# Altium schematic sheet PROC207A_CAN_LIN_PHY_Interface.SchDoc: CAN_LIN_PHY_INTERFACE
size 431 x 279 mm; Date: Not shown in title block; ApprovedBy: Not shown in title block; CheckedBy: Not shown in title block; Author: Not shown in title block; CompanyName: Not shown in title block; DrawnBy: Mistral; Engineer: Not shown in title block; Organization: Not shown in title block; Address1: Not shown in title block; Address2: Not shown in title block; Address3: Not shown in title block; Address4: Not shown in title block; DocumentNumber: 13; Revision: Use project parameter SCH_Rev; SheetNumber: 14; SheetTotal: 18; PageSetup: Record=PageOptions¦CenterHorizontal=True¦CenterVertical=True¦PrintScale=1.00¦XCorrection=1.00¦YCorrection=1.00¦PrintKind=0¦BorderSize=5000000¦LeftOffset=0¦BottomOffset=0¦Orientation=2¦PaperLength=1000¦PaperWidth=1000¦Scale=100¦PaperSource=15¦PrintQuality=600¦MediaType=1¦DitherType=10¦PaperKind=Letter¦PrintScaleMode=1
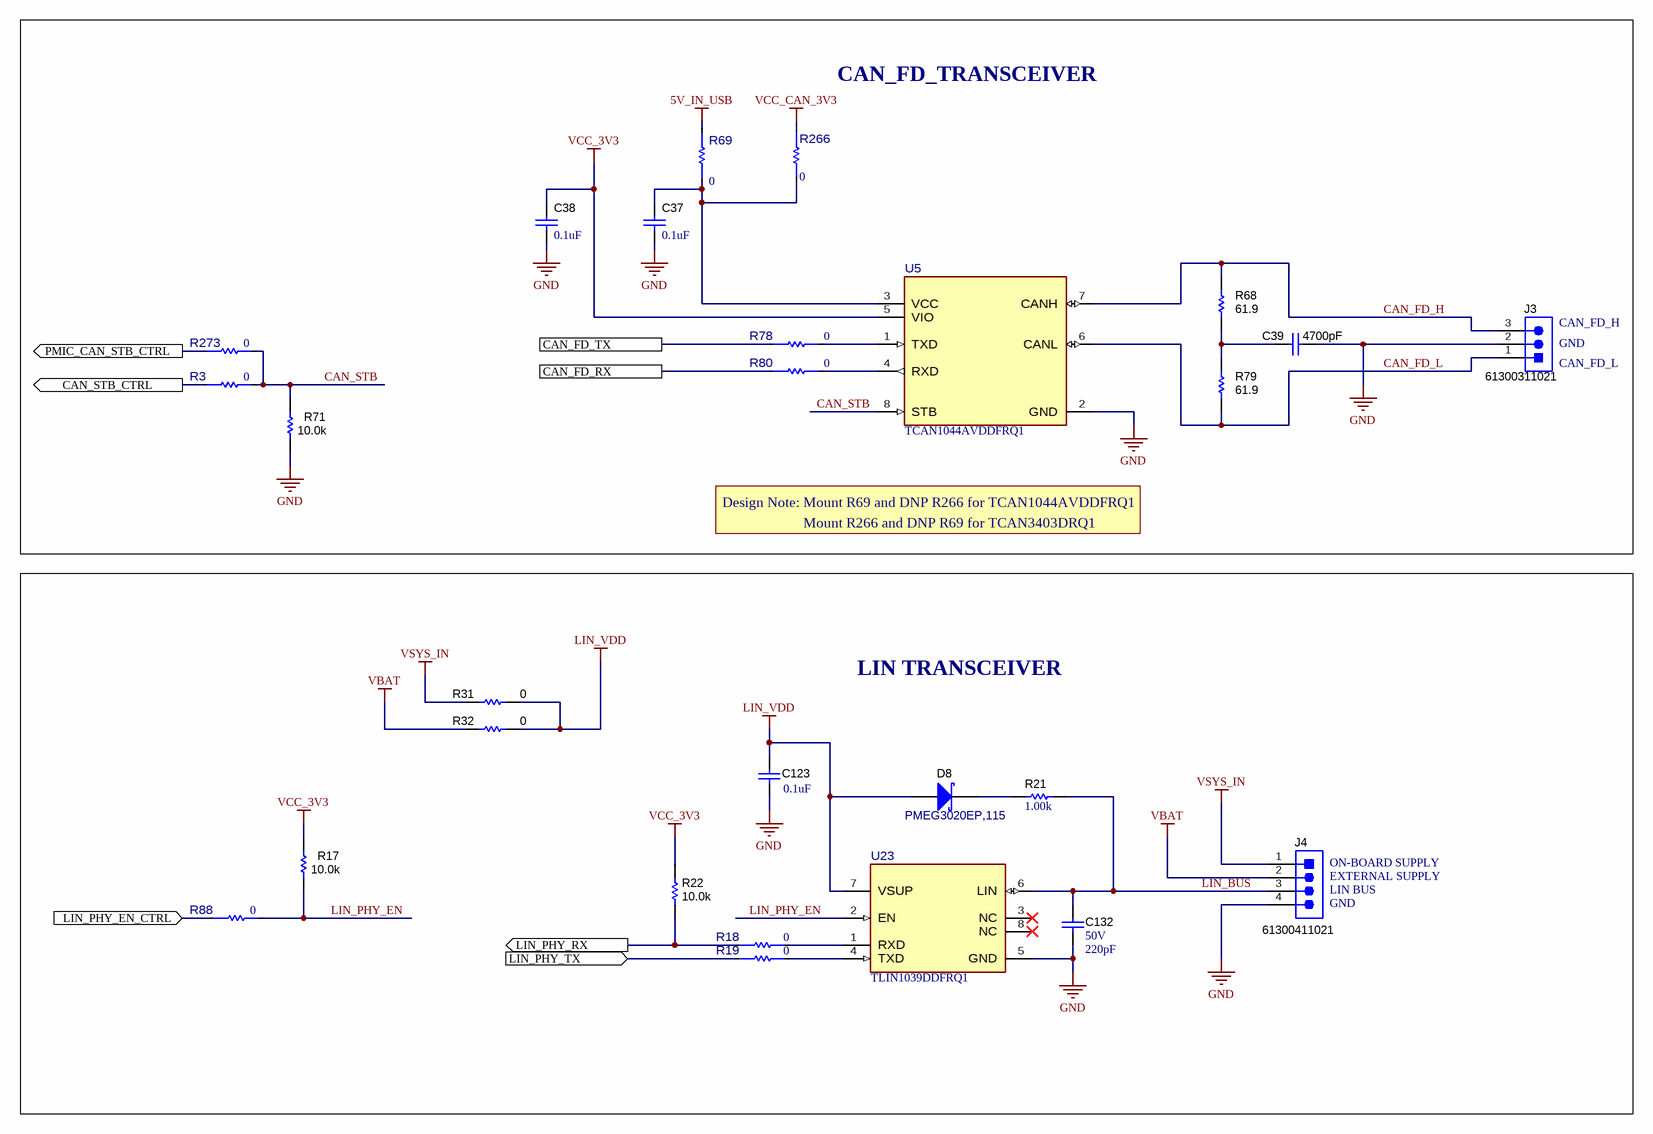
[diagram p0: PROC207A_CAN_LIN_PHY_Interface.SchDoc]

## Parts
C37  ValueDisplayed: 0.1uF  [0402]  (hidden comment: GCM155R71H104KE02D)
C38  ValueDisplayed: 0.1uF  [0402]  (hidden comment: GCM155R71H104KE02D)
C39  ValueDisplayed: 4700pF  [0402L]  (hidden comment: GCM155R71H472KA37D)
C123  ValueDisplayed: 0.1uF  [0402]  (hidden comment: GCM155R71H104KE02D)
C132  VDC_V: 50V  ValueDisplayed: 220pF  [0402]  (hidden comment: 885012005063)
D8  PMEG3020EP,115  [SOD-128]
J3  61300311021  [Wurth_61300311021]
J4  61300411021  [Wurth_61300411021]
R3  value 0  [FP-ERJ-2GE0R00X_0402-MFG]  (hidden comment: ERJ-2GE0R00X)
R17  ValueDisplayed: 10.0k  [0402L]  (hidden comment: CRCW040210K0FKED)
R18  value 0  [FP-ERJ-2GE0R00X_0402-MFG]  (hidden comment: ERJ-2GE0R00X)
R19  value 0  [FP-ERJ-2GE0R00X_0402-MFG]  (hidden comment: ERJ-2GE0R00X)
R21  ValueDisplayed: 1.00k  [0402]  (hidden comment: ERJ-2RKF1001X)
R22  ValueDisplayed: 10.0k  [0402L]  (hidden comment: CRCW040210K0FKED)
R31  ValueDisplayed: 0  [0603]  (hidden comment: MCT06030Z0000ZP500)
R32  ValueDisplayed: 0  [0603]  (hidden comment: MCT06030Z0000ZP500)
R68  ValueDisplayed: 61.9  [0402L]  (hidden comment: CRCW040261R9FKED)
R69  value 0  [FP-ERJ-2GE0R00X_0402-MFG]  (hidden comment: ERJ-2GE0R00X)
R71  ValueDisplayed: 10.0k  [0402L]  (hidden comment: CRCW040210K0FKED)
R78  value 0  [FP-ERJ-2GE0R00X_0402-MFG]  (hidden comment: ERJ-2GE0R00X)
R79  ValueDisplayed: 61.9  [0402L]  (hidden comment: CRCW040261R9FKED)
R80  value 0  [FP-ERJ-2GE0R00X_0402-MFG]  (hidden comment: ERJ-2GE0R00X)
R88  value 0  [FP-ERJ-2GE0R00X_0402-MFG]  (hidden comment: ERJ-2GE0R00X)
R266  value 0  [FP-ERJ-2GE0R00X_0402-MFG]  (hidden comment: ERJ-2GE0R00X)
R273  value 0  [FP-ERJ-2GE0R00X_0402-MFG]  (hidden comment: ERJ-2GE0R00X)
U5  TCAN1044AVDDFRQ1  [DDF0008A-MFG]
U23  TLIN1039DDFRQ1  [DDF0008A-MFG]

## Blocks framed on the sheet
CAN_FD_TRANSCEIVER: C37-C39 J3 R3 R68 R69 R71 R78-R80 R266 R273 U5
LIN TRANSCEIVER: C123 C132 D8 J4 R17-R19 R21 R22 R31 R32 R88 U23

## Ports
CAN_FD_RX, CAN_FD_TX, CAN_STB_CTRL (out), LIN_PHY_EN_CTRL (in), LIN_PHY_RX (out), LIN_PHY_TX (in), PMIC_CAN_STB_CTRL (out)

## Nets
5V_IN_USB: R69.2
GND: C37.1 C38.1 C39.1 C123.2 C132.2 J3.2 J4.4 R71.1 U5.2(GND) U23.5(GND)
LIN_VDD: C123.1 D8.2(A) R31.2 R32.2 U23.7(VSUP)
VBAT: J4.2 R32.1
VCC_3V3: C38.2 R17.2 R22.2 U5.5(VIO)
VCC_CAN_3V3: R266.1
VSYS_IN: J4.1 R31.1
CAN_FD_H: J3.3 R68.2 U5.7(CANH)
CAN_FD_L: J3.1 R79.1 U5.6(CANL)
CAN_FD_RX: R80.1 ; port CAN_FD_RX
CAN_FD_TX: R78.1 ; port CAN_FD_TX
CAN_STB: R3.2 R71.2 R273.2 U5.8(STB)
CAN_STB_CTRL: R3.1 ; port CAN_STB_CTRL
LIN_BUS: C132.1 J4.3 R21.1 U23.6(LIN)
LIN_PHY_EN: R17.1 R88.2 U23.2(EN)
LIN_PHY_EN_CTRL: R88.1 ; port LIN_PHY_EN_CTRL
LIN_PHY_RX: R18.1 R22.1 ; port LIN_PHY_RX
LIN_PHY_TX: R19.1 ; port LIN_PHY_TX
PMIC_CAN_STB_CTRL: R273.1 ; port PMIC_CAN_STB_CTRL
NetC37_2: C37.2 R69.1 R266.2 U5.3(VCC)
NetC39_2: C39.2 R68.1 R79.2
NetD8_1: D8.1(K) R21.2
NetR18_2: R18.2 U23.1(RXD)
NetR19_2: R19.2 U23.4(TXD)
NetR78_2: R78.2 U5.1(TXD)
NetR80_2: R80.2 U5.4(RXD)

Not connected (* = marked no-connect by the designer): U23 3(NC)* 8(NC)*

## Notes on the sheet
- (near J3) CAN_FD_H
- (near J3) GND
- (near J3) CAN_FD_L
- Design Note: Mount R69 and DNP R266 for TCAN1044AVDDFRQ1
- Mount R266 and DNP R69 for TCAN3403DRQ1
- (near J4) ON-BOARD SUPPLY
- (near J4) EXTERNAL SUPPLY
- (near J4) LIN BUS
- (near J4) GND

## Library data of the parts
C37 C38 = CMP-0006356-2: CAP, CERM, 0.1 uF, 50 V, +/- 10%, X7R, AEC-Q200 Grade 1, 0402; Manufacturer: MuRata; TaMin_C: -55°C; Polarized: N; SizeAreaWB_mm2: 3; U/M: EA; Value: 0.1uF; TaMax_C: 125°C; SizeZ_mm: 0.6; SizeX_mm: 1; SizeY_mm: 0.5; Value2: 50V; AEC Qualified: Y; Cap_F: 100nF; AEC Category: Q200; Value1: Unknown
C39 = CMP-0006361-2: CAP, CERM, 4700 pF, 50 V, +/- 10%, X7R, AEC-Q200 Grade 1, 0402; Manufacturer: MuRata; TaMin_C: -55°C; Polarized: N; SizeAreaWB_mm2: 3; Value1: Unknown; U/M: EA; Value: 4700pF; TaMax_C: 125°C; SizeZ_mm: 0.6; SizeX_mm: 1; SizeY_mm: 0.5; Cap_Case: 0402; Value2: 50V; AEC Qualified: Y; Cap_F: 4.7nF; AEC Category: Q200
C123 = CMP-0006356-2: CAP, CERM, 0.1 uF, 50 V, +/- 10%, X7R, AEC-Q200 Grade 1, 0402; Manufacturer: MuRata; TaMin_C: -55°C; Polarized: N; SizeAreaWB_mm2: 3; Value1: Unknown; U/M: EA; Value: 0.1uF; TaMax_C: 125°C; SizeZ_mm: 0.6; SizeX_mm: 1; SizeY_mm: 0.5; Value2: 50V; AEC Qualified: Y; Cap_F: 100nF; AEC Category: Q200
C132 = CMP-0006218-2: CAP, CERM, 220 pF, 50 V, +/- 5%, C0G/NP0, 0402; Manufacturer: Wurth Elektronik; TaMin_C: -55°C; Polarized: N; SizeAreaWB_mm2: 3; Value1: Unknown; U/M: EA; Value: 220pF; TaMax_C: 125°C; SizeZ_mm: 0.6; SizeX_mm: 1; SizeY_mm: 0.5; AEC Category: Q200
D8 = CMP-0078758-2: Diode, Schottky, 30 V, 2 A, AEC-Q101, SOD-128; Manufacturer: Nexperia; Value2: 0.36V; SizeAreaWB_mm2: 19.6; Io_A: 2A; Value: 30V; AEC Qualified: Y; TJmax_C: 150°C; SizeX_mm: 4.6; AEC Category: Q101; SizeY_mm: 2.5; SizeArea_mm2: 11.5; Vf_V: 3.6dV; SizeZ_mm: 1.1
J3 = CMP-0054795-1: Header, 2.54 mm, 3x1, Gold, R/A, TH; Manufacturer: Wurth Elektronik; CNHeader: TRUE; Shrouded: N; Gender: Male; Row_Count: 1; Pitch_mm: 2.54; CT: FALSE
J4 = CMP-0054797-1: Header, 2.54 mm, 4x1, Gold, R/A, TH; Manufacturer: Wurth Elektronik; CNHeader: TRUE; Shrouded: N; Gender: Male; Row_Count: 1; Pitch_mm: 2.54; CT: FALSE
R3 R18 R19 R69 R78 R80 R88 R266 R273 = CMP-0002710-1: 0 Ohms Jumper Chip Resistor 0402 (1005 Metric) Automotive AEC-Q200 Thick Film; Manufacturer: Panasonic; SizeZ_mm: 0.4mm; AEC Qualified: Yes; AEC Grade: Grade 0; Power: 100mW
R17 R22 R71 = CMP-0025958-3: RES, 10.0 k, 1%, 0.063 W, AEC-Q200 Grade 0, 0402; Manufacturer: Vishay-Dale; Power_W: 63mW; TempCo: 100 ppm/C; Value_Code: 10k0; Value: 10.0k; EIA_Code: E96; Res_ohm: 10k; SizeX_mm: 1; SizeY_mm: 0.5; SizeZ_mm: 0.6; Value2: 0.063W; AEC Qualified: Y; VDC_V: 50V; AEC Category: Q200; AEC Grade: 0
R21 = CMP-0026657-1: RES, 1.00 k, 1%, 0.1 W, 0402; Manufacturer: Panasonic; Power_W: 100mW; TempCo: 100 ppm/C; Value_Code: 1k00; Value: 1.00k; EIA_Code: E96; Res_ohm: 1k; SizeX_mm: 1; SizeY_mm: 0.5; SizeZ_mm: 0.6; Value2: 0.1W; VDC_V: 50V; AEC Category: Q200; U/M: EA
R31 R32 = CMP-0025884-3: RES, 0, 5%, 0.125 W, 0603; Manufacturer: Vishay/Beyschlag; Power_W: 125mW; TempCo: ppm/C; Value_Code: 0000; U/M: EA; Value: 0; EIA_Code: E24; SizeX_mm: 1.6; SizeY_mm: 0.8; SizeZ_mm: 1; Value2: 0.125W; SizeArea_mm2: 1.28; CompType: Resistor; AEC Qualified: N; AEC Category: Q200; INSTALATION: DNP
R68 R79 = CMP-0026491-2: RES, 61.9, 1%, 0.063 W, AEC-Q200 Grade 0, 0402; Manufacturer: Vishay-Dale; Power_W: 63mW; TempCo: 100 ppm/C; Value_Code: 61R9; Value: 61.9; EIA_Code: E96; SizeX_mm: 1; SizeY_mm: 0.5; SizeZ_mm: 0.6; Value2: 0.063W; AEC Qualified: Y; VDC_V: 50V; AEC Category: Q200; AEC Grade: 0
U5 = CMP-0122870-1: Enhanced automotive CAN transceiver with standby and 1.8-V I/O support 8-SOT-23-THIN -40 to 150; Manufacturer: Texas Instruments; SizeZ_mm: 1.1mm; AEC Qualified: Yes; AEC Grade: Grade 1; Max Supply Voltage: 5.5V; Min Supply Voltage: 1.7V; Standoff Height: 0mm; TJmax_C: +150°C
U23 = CMP-0090433-1: Local Interconnect Network (LIN) Transceiver with Dominant State Timeout; Manufacturer: Texas Instruments; Max Supply Voltage: 36V; SizeZ_mm: 1.1mm; Min Supply Voltage: 4.5V; Standoff Height: 0mm; Nominal Supply Current: 0.3-1.2mA; AEC Grade: Grade 0; TJmax_C: +150°C; Interface: UART,LIN,SCI; AEC Qualified: Yes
